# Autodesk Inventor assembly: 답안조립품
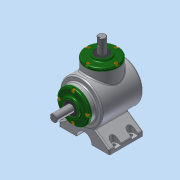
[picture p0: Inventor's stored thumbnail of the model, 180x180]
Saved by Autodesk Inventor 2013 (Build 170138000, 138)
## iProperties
Created: 2017-04
Part Number: 답안조립품
Document SubType Name: Assembly
Designer: narae
Author: narae
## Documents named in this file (14)
- C:\Users\narae\Desktop\470408V1019\답안조립품.iam
- C:\Users\narae\Desktop\470408V1019\본체.ipt
- C:\Users\narae\Desktop\470408V1019\메인 축.ipt
- 메인 축.ipt
- C:\Users\narae\Desktop\470408V1019\키 5x5.ipt
- C:\Users\narae\Desktop\470408V1019\메인 베벨기어.ipt
- C:\Users\narae\Desktop\470408V1019\베어링 6203.ipt
- C:\Users\narae\Desktop\470408V1019\커버.ipt
- C:\Users\narae\Desktop\470408V1019\볼트 M4.ipt
- C:\Users\narae\Desktop\470408V1019\오일실 17 32 8.ipt
- C:\Users\narae\Desktop\470408V1019\서브 축.ipt
- 서브 축.ipt
- C:\Users\narae\Desktop\470408V1019\키 4x4.ipt
- C:\Users\narae\Desktop\470408V1019\서브 베벨기어.ipt
